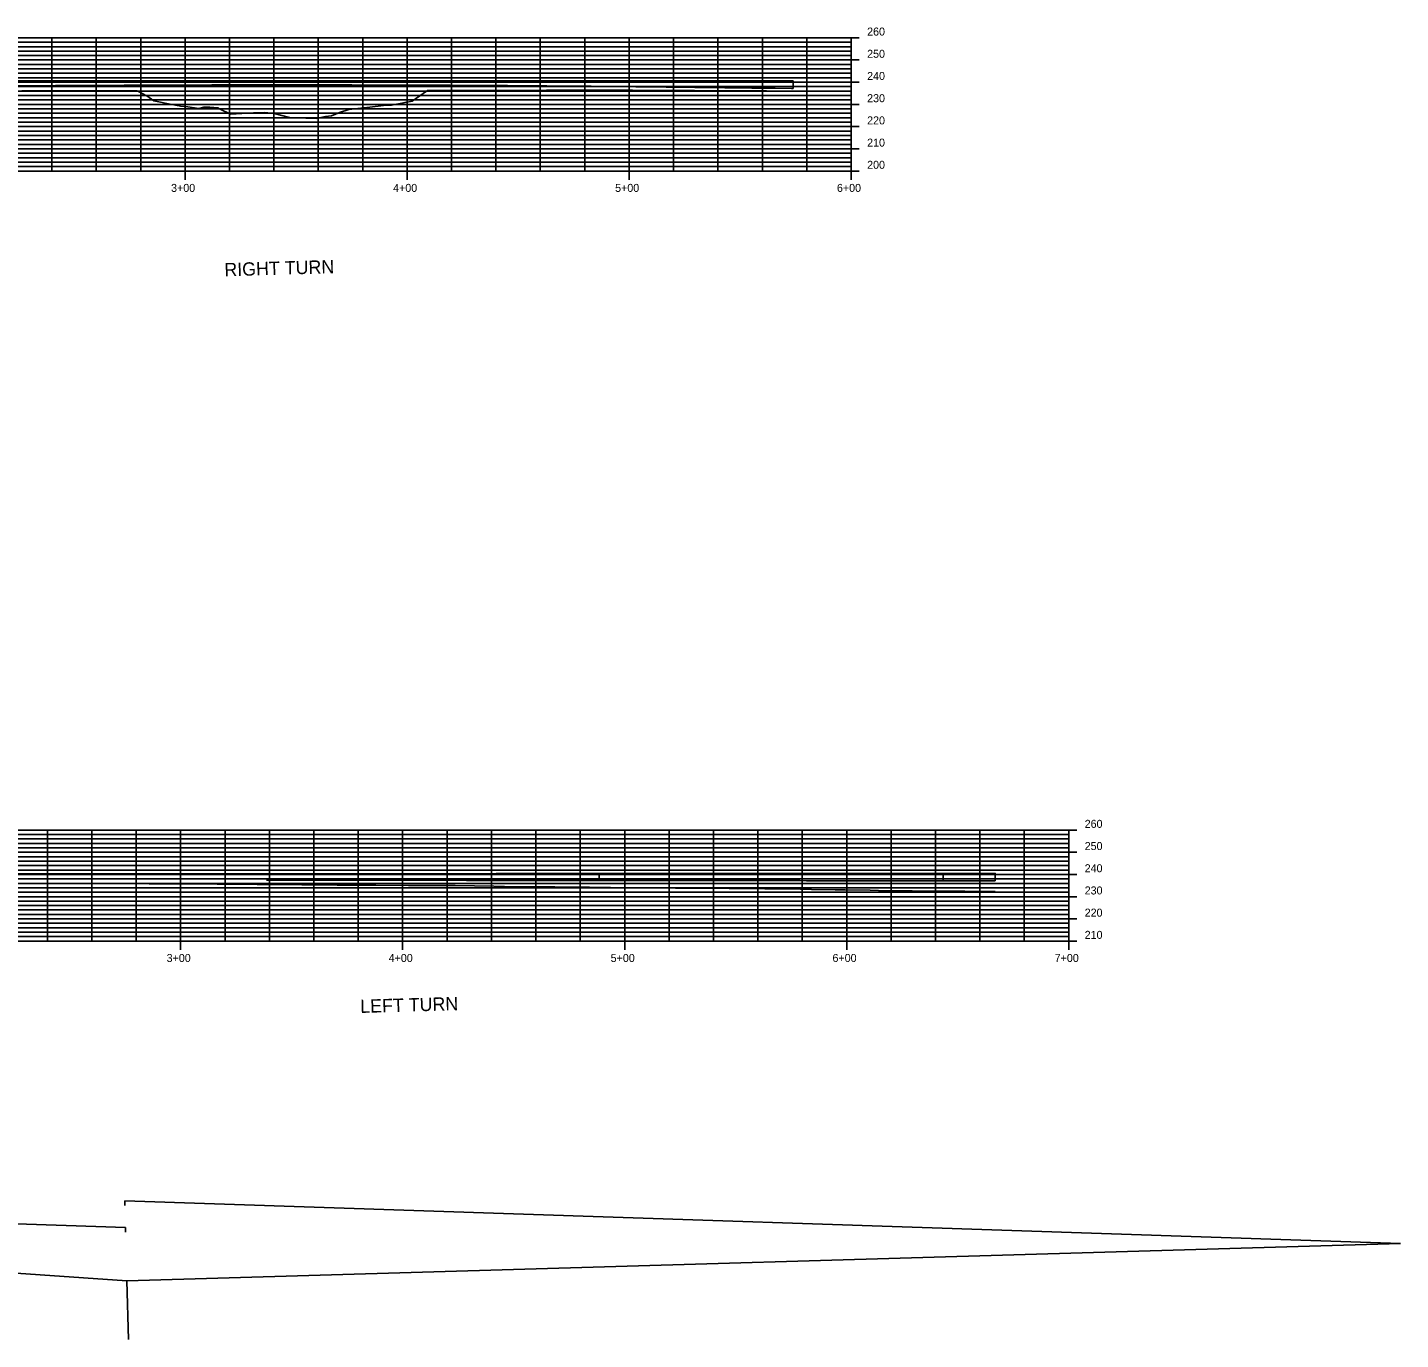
# Model space of a CAD drawing. Extents: x 977011 to 983719, y 1526280 to 1528290.
# Drawn here: x 977632 to 978250, y 1527699 to 1528290 of the extents above; entities that cross this region are included whole.
import ezdxf

# ---------------------------------------------------------------- set-up
doc = ezdxf.new("R2010")
doc.units = 0
for name, color, linetype in [('B_Concrete', 7, 'Continuous'), ('R_Axis', 7, 'Continuous'), ('R_Axis Annot', 7, 'Continuous'), ('R_Exist Surface', 7, 'Continuous'), ('R_Grid', 7, 'Continuous'), ('R_Vert Alg', 7, 'Continuous')]:
    doc.layers.add(name, color=color, linetype=linetype)

msp = doc.modelspace()

# ---------------------------------------------------------------- linework, layer by layer
at = {"layer": 'B_Concrete'}
for p, q in [((977402.95, 1528265.57), (977976.87, 1528265.62)), ((977976.87, 1528262.12), (977976.87, 1528265.62)), ((978067.84, 1527908.78), (977400.94, 1527908.34)), ((977889.47, 1527905.45), (977889.47, 1527908.12)), ((978044.4, 1527905.31), (978044.4, 1527907.98)), ((978067.84, 1527905.28), (978067.84, 1527908.78)), ((977011.43, 1527771.4), (977676.06, 1527749.18)), ((977676.72, 1527725.15), (977011.43, 1527771.4)), ((978250.41, 1527741.99), (977675.73, 1527761.2)), ((977675.73, 1527761.2), (977675.73, 1527759.08)), ((977676.06, 1527749.18), (977676.06, 1527747.06)), ((977676.72, 1527725.15), (978250.41, 1527741.99)), ((977677.46, 1527698.72), (977676.72, 1527725.15))]:
    msp.add_line(p, q, dxfattribs=at)
at = {"layer": 'R_Axis'}
for p, q in [((978002.95, 1528224.95), (978002.95, 1528284.95)), ((977402.95, 1528224.95), (978002.95, 1528224.95)), ((978100.94, 1527878.16), (978100.94, 1527928.16)), ((977400.94, 1527878.16), (978100.94, 1527878.16))]:
    msp.add_line(p, q, dxfattribs=at)
at = {"layer": 'R_Exist Surface'}
for points in [[(977629.34, 1528261), (977637.08, 1528261.02), (977644.34, 1528261.08), (977651.22, 1528261.1), (977659.37, 1528261.13), (977669.24, 1528261.02), (977678.47, 1528261.04), (977681.2, 1528261.09), (977682.63, 1528260.48), (977685.32, 1528259.01), (977685.7, 1528258.75), (977688.84, 1528256.56), (977696.98, 1528254.95), (977699.48, 1528254.4), (977700.8, 1528254.19), (977704.18, 1528253.84), (977709.16, 1528253.17), (977711.42, 1528253.74), (977714.09, 1528253.69), (977717.64, 1528253.44), (977718.76, 1528252.74), (977723.47, 1528250.51), (977733.77, 1528251.21), (977738.87, 1528251.32), (977743.04, 1528250.84), (977749.9, 1528249), (977757.3, 1528248.76), (977761.99, 1528248.62), (977766.2, 1528249.43), (977768.87, 1528249.84), (977772.56, 1528251.27), (977776.71, 1528252.73), (977786.15, 1528253.74), (977792.34, 1528254.4), (977795.9, 1528254.66), (977795.92, 1528254.66), (977802.06, 1528255.81), (977805.22, 1528256.39), (977810.11, 1528259.81), (977812.14, 1528261.26), (977825.43, 1528261.24), (977827.17, 1528261.24), (977828.38, 1528261.24), (977831.66, 1528261.25), (977842.2, 1528261.26), (977847.47, 1528261.26), (977857.23, 1528261.28), (977865.78, 1528261.29), (977872.26, 1528261.31), (977875.94, 1528261.31), (977887.3, 1528261.34), (977895.41, 1528261.31), (977902.33, 1528261.31), (977904.43, 1528261.31), (977914.05, 1528261.28), (977915.55, 1528261.27), (977917.36, 1528261.27), (977917.73, 1528261.27), (977917.77, 1528261.27), (977927.86, 1528261.2), (977932.4, 1528261.18), (977939.61, 1528261.13), (977947.43, 1528261.09), (977959.84, 1528261.01), (977962.41, 1528261), (977964.82, 1528260.99), (977976.87, 1528260.95)], [(977631.7, 1527904.16), (977641.64, 1527904.14), (977653.16, 1527904.1), (977656.71, 1527904.09), (977659.73, 1527904.08), (977671.72, 1527904.06), (977674.37, 1527904.05), (977686.73, 1527904), (977688.53, 1527903.99), (977701.74, 1527903.93), (977711.1, 1527903.91), (977715.58, 1527903.88), (977717.46, 1527903.86), (977728.42, 1527903.75), (977735.37, 1527903.68), (977741.58, 1527903.61), (977755.46, 1527903.46), (977755.92, 1527903.46), (977757.35, 1527903.46), (977771.46, 1527903.36), (977772.3, 1527903.37), (977787.45, 1527903.28), (977788.84, 1527903.3), (977803.62, 1527903.22), (977805.36, 1527903.23), (977819.9, 1527903.16), (977821.88, 1527903.17), (977824.58, 1527903.12), (977842.01, 1527902.93), (977846.77, 1527902.81), (977861.92, 1527902.63), (977869.48, 1527902.57), (977885.08, 1527902.4), (977894.61, 1527902.32), (977908.32, 1527902.17), (977915.5, 1527902.08), (977923.82, 1527902.06), (977931.74, 1527901.96), (977939.29, 1527901.93), (977947.94, 1527901.82), (977954.72, 1527901.79), (977964.1, 1527901.66), (977970.11, 1527901.63), (977980.1, 1527901.49), (977985.13, 1527901.4), (977995.77, 1527901.26), (978000.18, 1527901.18), (978011.48, 1527901.03), (978015.27, 1527900.96), (978027.21, 1527900.8), (978030.39, 1527900.74), (978034.98, 1527900.69), (978054.21, 1527900.61), (978061.38, 1527900.53), (978067.84, 1527900.5)]]:
    msp.add_lwpolyline(points, dxfattribs=at)
at = {"layer": 'R_Grid'}
for p, q in [((977402.95, 1528284.95), (978002.95, 1528284.95)), ((977402.95, 1528284.95), (978002.95, 1528284.95)), ((977642.95, 1528224.95), (977642.95, 1528284.95)), ((977662.95, 1528224.95), (977662.95, 1528284.95)), ((977682.95, 1528224.95), (977682.95, 1528284.95)), ((977702.95, 1528224.95), (977702.95, 1528284.95)), ((977722.95, 1528224.95), (977722.95, 1528284.95)), ((977742.95, 1528224.95), (977742.95, 1528284.95)), ((977762.95, 1528224.95), (977762.95, 1528284.95)), ((977782.95, 1528224.95), (977782.95, 1528284.95)), ((977802.95, 1528224.95), (977802.95, 1528284.95)), ((977822.95, 1528224.95), (977822.95, 1528284.95)), ((977842.95, 1528224.95), (977842.95, 1528284.95)), ((977862.95, 1528224.95), (977862.95, 1528284.95)), ((977882.95, 1528224.95), (977882.95, 1528284.95)), ((977902.95, 1528224.95), (977902.95, 1528284.95)), ((977922.95, 1528224.95), (977922.95, 1528284.95)), ((977942.95, 1528224.95), (977942.95, 1528284.95)), ((977962.95, 1528224.95), (977962.95, 1528284.95)), ((977982.95, 1528224.95), (977982.95, 1528284.95)), ((978006.55, 1528284.95), (978002.95, 1528284.95)), ((978006.55, 1528284.95), (978002.95, 1528284.95)), ((977402.95, 1528282.95), (978002.95, 1528282.95)), ((977402.95, 1528280.95), (978002.95, 1528280.95)), ((977402.95, 1528278.95), (978002.95, 1528278.95)), ((978002.95, 1528282.95), (978001.15, 1528282.95)), ((978002.95, 1528280.95), (978001.15, 1528280.95)), ((978002.95, 1528278.95), (978001.15, 1528278.95)), ((977402.95, 1528276.95), (978002.95, 1528276.95)), ((977402.95, 1528274.95), (978002.95, 1528274.95)), ((977402.95, 1528272.95), (978002.95, 1528272.95)), ((978002.95, 1528276.95), (978001.15, 1528276.95)), ((978002.95, 1528272.95), (978001.15, 1528272.95)), ((978006.55, 1528274.95), (978002.95, 1528274.95)), ((977402.95, 1528270.95), (978002.95, 1528270.95)), ((977402.95, 1528268.95), (978002.95, 1528268.95)), ((977402.95, 1528266.95), (978002.95, 1528266.95)), ((978002.95, 1528270.95), (978001.15, 1528270.95)), ((978002.95, 1528268.95), (978001.15, 1528268.95)), ((978002.95, 1528266.95), (978001.15, 1528266.95)), ((977402.95, 1528264.95), (978002.95, 1528264.95)), ((977402.95, 1528262.95), (978002.95, 1528262.95)), ((977402.95, 1528260.95), (978002.95, 1528260.95)), ((978002.95, 1528262.95), (978001.15, 1528262.95)), ((978002.95, 1528260.95), (978001.15, 1528260.95)), ((978006.55, 1528264.95), (978002.95, 1528264.95)), ((977402.95, 1528258.95), (978002.95, 1528258.95)), ((977402.95, 1528256.95), (978002.95, 1528256.95)), ((977402.95, 1528254.95), (978002.95, 1528254.95)), ((977402.95, 1528252.95), (978002.95, 1528252.95)), ((978002.95, 1528258.95), (978001.15, 1528258.95)), ((978002.95, 1528256.95), (978001.15, 1528256.95)), ((978002.95, 1528252.95), (978001.15, 1528252.95)), ((978006.55, 1528254.95), (978002.95, 1528254.95)), ((977402.95, 1528250.95), (978002.95, 1528250.95)), ((977402.95, 1528248.95), (978002.95, 1528248.95)), ((977402.95, 1528246.95), (978002.95, 1528246.95)), ((978002.95, 1528250.95), (978001.15, 1528250.95)), ((978002.95, 1528248.95), (978001.15, 1528248.95)), ((978002.95, 1528246.95), (978001.15, 1528246.95)), ((977402.95, 1528244.95), (978002.95, 1528244.95)), ((977402.95, 1528242.95), (978002.95, 1528242.95)), ((977402.95, 1528240.95), (978002.95, 1528240.95)), ((978002.95, 1528242.95), (978001.15, 1528242.95)), ((978002.95, 1528240.95), (978001.15, 1528240.95)), ((978006.55, 1528244.95), (978002.95, 1528244.95)), ((977402.95, 1528238.95), (978002.95, 1528238.95)), ((977402.95, 1528236.95), (978002.95, 1528236.95)), ((977402.95, 1528234.95), (978002.95, 1528234.95)), ((978002.95, 1528238.95), (978001.15, 1528238.95)), ((978002.95, 1528236.95), (978001.15, 1528236.95)), ((978006.55, 1528234.95), (978002.95, 1528234.95)), ((977402.95, 1528232.95), (978002.95, 1528232.95)), ((977402.95, 1528230.95), (978002.95, 1528230.95)), ((977402.95, 1528228.95), (978002.95, 1528228.95)), ((978002.95, 1528232.95), (978001.15, 1528232.95)), ((978002.95, 1528230.95), (978001.15, 1528230.95)), ((978002.95, 1528228.95), (978001.15, 1528228.95)), ((977402.95, 1528226.95), (978002.95, 1528226.95)), ((977702.95, 1528220.95), (977702.95, 1528224.95)), ((977802.95, 1528220.95), (977802.95, 1528224.95)), ((977902.95, 1528220.95), (977902.95, 1528224.95)), ((978002.95, 1528226.95), (978001.15, 1528226.95)), ((978006.55, 1528224.95), (978002.95, 1528224.95)), ((978002.95, 1528220.95), (978002.95, 1528224.95)), ((977400.94, 1527928.16), (978100.94, 1527928.16)), ((977400.94, 1527928.16), (978100.94, 1527928.16)), ((977400.94, 1527926.16), (978100.94, 1527926.16)), ((977640.94, 1527878.16), (977640.94, 1527928.16)), ((977660.94, 1527878.16), (977660.94, 1527928.16)), ((977680.94, 1527878.16), (977680.94, 1527928.16)), ((977700.94, 1527878.16), (977700.94, 1527928.16)), ((977720.94, 1527878.16), (977720.94, 1527928.16)), ((977740.94, 1527878.16), (977740.94, 1527928.16)), ((977760.94, 1527878.16), (977760.94, 1527928.16)), ((977780.94, 1527878.16), (977780.94, 1527928.16)), ((977800.94, 1527878.16), (977800.94, 1527928.16)), ((977820.94, 1527878.16), (977820.94, 1527928.16)), ((977840.94, 1527878.16), (977840.94, 1527928.16)), ((977860.94, 1527878.16), (977860.94, 1527928.16)), ((977880.94, 1527878.16), (977880.94, 1527928.16)), ((977900.94, 1527878.16), (977900.94, 1527928.16)), ((977920.94, 1527878.16), (977920.94, 1527928.16)), ((977940.94, 1527878.16), (977940.94, 1527928.16)), ((977960.94, 1527878.16), (977960.94, 1527928.16)), ((977980.94, 1527878.16), (977980.94, 1527928.16)), ((978000.94, 1527878.16), (978000.94, 1527928.16)), ((978020.94, 1527878.16), (978020.94, 1527928.16)), ((978040.94, 1527878.16), (978040.94, 1527928.16)), ((978060.94, 1527878.16), (978060.94, 1527928.16)), ((978080.94, 1527878.16), (978080.94, 1527928.16)), ((978100.94, 1527926.16), (978099.14, 1527926.16)), ((978104.54, 1527928.16), (978100.94, 1527928.16)), ((978104.54, 1527928.16), (978100.94, 1527928.16)), ((977400.94, 1527924.16), (978100.94, 1527924.16)), ((977400.94, 1527922.16), (978100.94, 1527922.16)), ((977400.94, 1527920.16), (978100.94, 1527920.16)), ((978100.94, 1527924.16), (978099.14, 1527924.16)), ((978100.94, 1527922.16), (978099.14, 1527922.16)), ((978100.94, 1527920.16), (978099.14, 1527920.16)), ((977400.94, 1527918.16), (978100.94, 1527918.16)), ((977400.94, 1527916.16), (978100.94, 1527916.16)), ((977400.94, 1527914.16), (978100.94, 1527914.16)), ((978100.94, 1527916.16), (978099.14, 1527916.16)), ((978100.94, 1527914.16), (978099.14, 1527914.16)), ((978104.54, 1527918.16), (978100.94, 1527918.16)), ((977400.94, 1527912.16), (978100.94, 1527912.16)), ((977400.94, 1527910.16), (978100.94, 1527910.16)), ((977400.94, 1527908.16), (978100.94, 1527908.16)), ((978100.94, 1527912.16), (978099.14, 1527912.16)), ((978100.94, 1527910.16), (978099.14, 1527910.16)), ((978104.54, 1527908.16), (978100.94, 1527908.16)), ((977400.94, 1527906.16), (978100.94, 1527906.16)), ((977400.94, 1527904.16), (978100.94, 1527904.16)), ((977400.94, 1527902.16), (978100.94, 1527902.16)), ((978100.94, 1527906.16), (978099.14, 1527906.16)), ((978100.94, 1527904.16), (978099.14, 1527904.16)), ((978100.94, 1527902.16), (978099.14, 1527902.16)), ((977400.94, 1527900.16), (978100.94, 1527900.16)), ((977400.94, 1527898.16), (978100.94, 1527898.16)), ((977400.94, 1527896.16), (978100.94, 1527896.16)), ((978100.94, 1527900.16), (978099.14, 1527900.16)), ((978100.94, 1527896.16), (978099.14, 1527896.16)), ((978104.54, 1527898.16), (978100.94, 1527898.16)), ((977400.94, 1527894.16), (978100.94, 1527894.16)), ((977400.94, 1527892.16), (978100.94, 1527892.16)), ((977400.94, 1527890.16), (978100.94, 1527890.16)), ((977400.94, 1527888.16), (978100.94, 1527888.16)), ((978100.94, 1527894.16), (978099.14, 1527894.16)), ((978100.94, 1527892.16), (978099.14, 1527892.16)), ((978100.94, 1527890.16), (978099.14, 1527890.16)), ((978104.54, 1527888.16), (978100.94, 1527888.16)), ((977400.94, 1527886.16), (978100.94, 1527886.16)), ((977400.94, 1527884.16), (978100.94, 1527884.16)), ((977400.94, 1527882.16), (978100.94, 1527882.16)), ((978100.94, 1527886.16), (978099.14, 1527886.16)), ((978100.94, 1527884.16), (978099.14, 1527884.16)), ((978100.94, 1527882.16), (978099.14, 1527882.16)), ((977400.94, 1527880.16), (978100.94, 1527880.16)), ((977700.94, 1527874.16), (977700.94, 1527878.16)), ((977800.94, 1527874.16), (977800.94, 1527878.16)), ((977900.94, 1527874.16), (977900.94, 1527878.16)), ((978000.94, 1527874.16), (978000.94, 1527878.16)), ((978100.94, 1527880.16), (978099.14, 1527880.16)), ((978104.54, 1527878.16), (978100.94, 1527878.16)), ((978100.94, 1527874.16), (978100.94, 1527878.16))]:
    msp.add_line(p, q, dxfattribs=at)
at = {"layer": 'R_Vert Alg'}
for points in [[(977625.39, 1528263.26), (977634.76, 1528263.33), (977635.41, 1528263.33), (977644.59, 1528263.4), (977645.43, 1528263.4), (977645.59, 1528263.4), (977647.28, 1528263.41), (977648.03, 1528263.42), (977655.45, 1528263.46), (977661.25, 1528263.49), (977668.74, 1528263.53), (977675.49, 1528263.57), (977675.5, 1528263.57), (977684.95, 1528263.61), (977689.91, 1528263.63), (977695.4, 1528263.65), (977695.54, 1528263.65), (977695.69, 1528263.65), (977705.16, 1528263.67), (977705.56, 1528263.68), (977705.56, 1528263.68), (977705.98, 1528263.68), (977714.92, 1528263.7), (977715.58, 1528263.7), (977716.27, 1528263.7), (977724.69, 1528263.71), (977725.6, 1528263.71), (977726.56, 1528263.72), (977734.45, 1528263.72), (977735.62, 1528263.72), (977735.62, 1528263.72), (977736.85, 1528263.72), (977744.22, 1528263.73), (977745.64, 1528263.73), (977745.64, 1528263.73), (977747.14, 1528263.73), (977753.98, 1528263.73), (977755.66, 1528263.73), (977755.66, 1528263.73), (977757.43, 1528263.72), (977763.74, 1528263.72), (977765.68, 1528263.72), (977765.68, 1528263.72), (977767.72, 1528263.71), (977773.51, 1528263.7), (977775.7, 1528263.7), (977775.7, 1528263.7), (977778, 1528263.69), (977783.27, 1528263.68), (977785.72, 1528263.68), (977788.29, 1528263.67), (977793.04, 1528263.66), (977795.74, 1528263.65), (977798.58, 1528263.64), (977802.8, 1528263.62), (977805.76, 1528263.61), (977808.87, 1528263.6), (977812.56, 1528263.59), (977815.78, 1528263.57), (977819.16, 1528263.56), (977822.33, 1528263.54), (977825.8, 1528263.52), (977825.8, 1528263.52), (977829.45, 1528263.5), (977832.09, 1528263.49), (977835.82, 1528263.47), (977835.82, 1528263.47), (977839.74, 1528263.45), (977841.86, 1528263.43), (977845.84, 1528263.41), (977845.84, 1528263.41), (977847.06, 1528263.4), (977848.21, 1528263.39), (977865.87, 1528263.27), (977870.53, 1528263.23), (977875.89, 1528263.19), (977880.41, 1528263.15), (977884.05, 1528263.12), (977885.1, 1528263.11), (977885.9, 1528263.1), (977890.18, 1528263.06), (977895.92, 1528263.01), (977900, 1528262.97), (977905.94, 1528262.91), (977907.18, 1528262.89), (977909.1, 1528262.87), (977913.35, 1528262.83), (977915.96, 1528262.8), (977919.65, 1528262.76), (977925.98, 1528262.69), (977932.57, 1528262.62), (977936, 1528262.58), (977939.3, 1528262.54), (977946.02, 1528262.46), (977949.12, 1528262.43), (977956.04, 1528262.35), (977958.28, 1528262.33), (977959.2, 1528262.32), (977964.15, 1528262.26), (977966.06, 1528262.24), (977968.77, 1528262.21), (977976.08, 1528262.13), (977976.87, 1528262.12)], [(977739.63, 1527905.59), (977739.85, 1527905.59), (977749.64, 1527905.58), (977749.98, 1527905.58), (977759.65, 1527905.57), (977760.1, 1527905.57), (977769.65, 1527905.56), (977778.99, 1527905.56), (977779.66, 1527905.55), (977780.34, 1527905.55), (977789.67, 1527905.55), (977790.47, 1527905.54), (977799.67, 1527905.54), (977808.67, 1527905.53), (977809.68, 1527905.53), (977810.71, 1527905.52), (977819.69, 1527905.52), (977820.83, 1527905.52), (977829.69, 1527905.51), (977838.35, 1527905.5), (977839.7, 1527905.5), (977841.08, 1527905.5), (977849.7, 1527905.49), (977858.14, 1527905.48), (977859.71, 1527905.48), (977861.32, 1527905.48), (977869.72, 1527905.47), (977871.44, 1527905.47), (977879.72, 1527905.46), (977887.82, 1527905.45), (977889.73, 1527905.45), (977891.69, 1527905.45), (977899.74, 1527905.44), (977901.81, 1527905.44), (977909.74, 1527905.43), (977911.93, 1527905.43), (977919.75, 1527905.42), (977922.05, 1527905.42), (977929.76, 1527905.41), (977937.28, 1527905.41), (977939.76, 1527905.4), (977942.3, 1527905.4), (977949.77, 1527905.39), (977957.07, 1527905.39), (977959.78, 1527905.38), (977966.96, 1527905.38), (977969.78, 1527905.38), (977972.67, 1527905.37), (977979.79, 1527905.37), (977982.79, 1527905.36), (977989.8, 1527905.36), (977992.91, 1527905.35), (977999.8, 1527905.35), (978003.03, 1527905.34), (978009.81, 1527905.34), (978016.43, 1527905.33), (978019.81, 1527905.33), (978023.28, 1527905.33), (978029.82, 1527905.32), (978033.4, 1527905.32), (978039.83, 1527905.31), (978046.11, 1527905.3), (978049.83, 1527905.3), (978053.64, 1527905.3), (978059.84, 1527905.29), (978063.31, 1527905.29), (978067.84, 1527905.28)]]:
    msp.add_lwpolyline(points, dxfattribs=at)

# ---------------------------------------------------------------- texts
at = {"layer": 'B_Concrete'}
for s, p in [('RIGHT TURN', (977720.72, 1528177.51)), ('LEFT TURN', (977781.91, 1527845.78))]:
    msp.add_text(s, height=6, rotation=1.66087, dxfattribs=at).set_placement(p)
at = {"layer": 'R_Axis Annot'}
for s, p in [('260', (978010.15, 1528285.95)), ('260', (978010.15, 1528285.95)), ('250', (978010.15, 1528275.95)), ('240', (978010.15, 1528265.95)), ('230', (978010.15, 1528255.95)), ('220', (978010.15, 1528245.95)), ('210', (978010.15, 1528235.95)), ('200', (978010.15, 1528225.95)), ('3+00', (977696.64, 1528215.55)), ('4+00', (977796.64, 1528215.55)), ('5+00', (977896.64, 1528215.55)), ('6+00', (977996.55, 1528215.55)), ('260', (978108.14, 1527929.16)), ('260', (978108.14, 1527929.16)), ('250', (978108.14, 1527919.16)), ('240', (978108.14, 1527909.16)), ('230', (978108.14, 1527899.16)), ('220', (978108.14, 1527889.16)), ('210', (978108.14, 1527879.16)), ('3+00', (977694.63, 1527868.76)), ('4+00', (977794.63, 1527868.76)), ('5+00', (977894.63, 1527868.76)), ('6+00', (977994.55, 1527868.76)), ('7+00', (978094.63, 1527868.76))]:
    msp.add_text(s, height=3.6, dxfattribs=at).set_placement(p)

doc.saveas('drawing.dxf')
